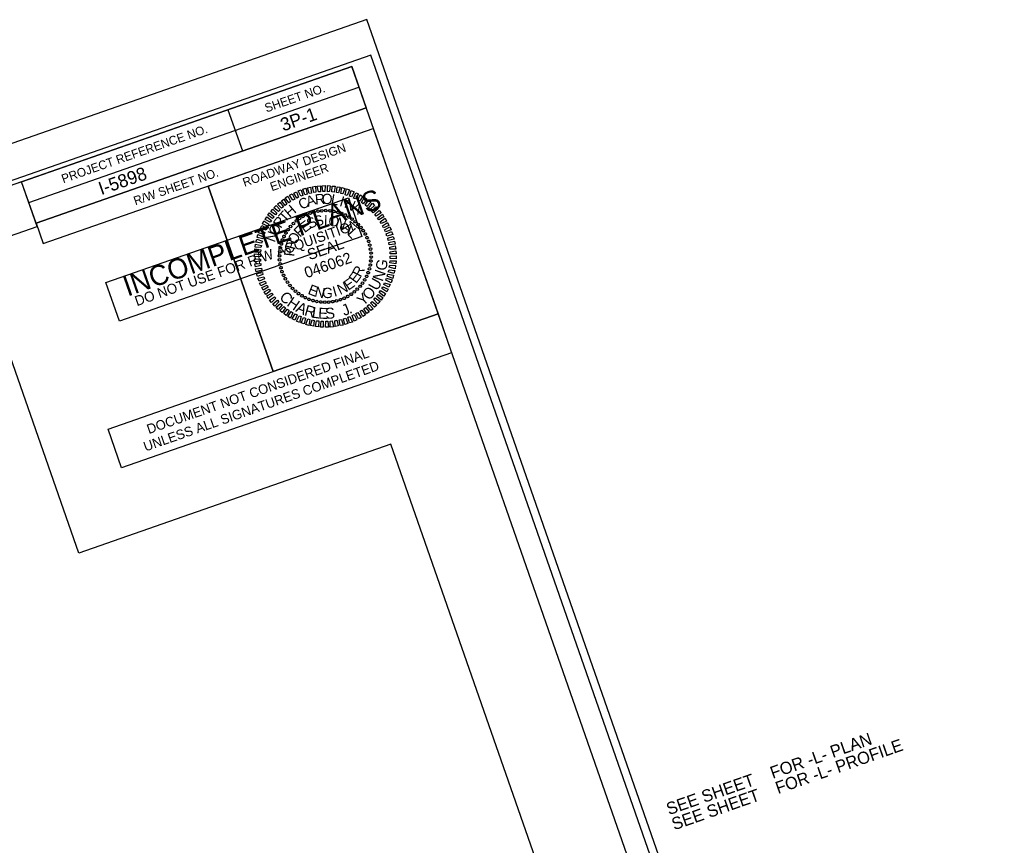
# Model space of a CAD drawing. Extents: x 1719383 to 1723601, y 969280 to 972080.
# Drawn here: x 1720774 to 1721334, y 970396 to 970869 of the extents above; entities that cross this region are included whole.
import ezdxf

# ---------------------------------------------------------------- set-up
doc = ezdxf.new("R2010")
doc.units = 0
for name, color, linetype in [('Default', 7, 'Continuous'), ('Old_Level_2', 7, 'Continuous'), ('Prop Dimension', 7, 'Continuous'), ('Prop Dimension Text', 7, 'Continuous'), ('Sheet Clip Boundary CELL', 7, 'Continuous'), ('Sheet Data Field CELL', 7, 'Continuous'), ('Sheet Plan CELL', 7, 'Continuous'), ('Sheet Plot Border Inside CELL', 7, 'Continuous'), ('Sheet Plot Border Outside CELL', 7, 'Continuous'), ('Sheet Sticker Exception Certification CELL', 7, 'Continuous'), ('Sheet Sticker Incomplete CELL', 7, 'Continuous')]:
    doc.layers.add(name, color=color, linetype=linetype)

msp = doc.modelspace()

# ---------------------------------------------------------------- linework, layer by layer
at = {"layer": 'Old_Level_2'}
for p, q in [((1720949.47, 970759.33), (1720949.47, 970759.33)), ((1720934.33, 970754.75), (1720934.33, 970754.75)), ((1720936.34, 970755.94), (1720936.34, 970755.94)), ((1720938.35, 970757.01), (1720938.35, 970757.01)), ((1720940.49, 970757.86), (1720940.49, 970757.86)), ((1720942.7, 970758.51), (1720942.7, 970758.51)), ((1720944.93, 970758.94), (1720944.93, 970758.94)), ((1720947.16, 970759.26), (1720947.16, 970759.26)), ((1720951.76, 970759.17), (1720951.76, 970759.17)), ((1720954.04, 970758.9), (1720954.04, 970758.9)), ((1720956.25, 970758.32), (1720956.25, 970758.32)), ((1720958.46, 970757.63), (1720958.46, 970757.63)), ((1720960.52, 970756.72), (1720960.52, 970756.72)), ((1720962.59, 970755.64), (1720962.59, 970755.64)), ((1720964.45, 970754.38), (1720964.45, 970754.38)), ((1720927.82, 970748.39), (1720927.82, 970748.39)), ((1720929.26, 970750.2), (1720929.26, 970750.2)), ((1720930.82, 970751.89), (1720930.82, 970751.89)), ((1720932.49, 970753.4), (1720932.49, 970753.4)), ((1720966.27, 970752.93), (1720966.27, 970752.93)), ((1720967.95, 970751.38), (1720967.95, 970751.38)), ((1720969.46, 970749.71), (1720969.46, 970749.71)), ((1720925.48, 970744.46), (1720925.48, 970744.46)), ((1720926.55, 970746.53), (1720926.55, 970746.53)), ((1720970.81, 970747.87), (1720970.81, 970747.87)), ((1720972, 970745.85), (1720972, 970745.85)), ((1720973.07, 970743.85), (1720973.07, 970743.85)), ((1720923.3, 970737.97), (1720923.3, 970737.97)), ((1720923.87, 970740.19), (1720923.87, 970740.19)), ((1720924.56, 970742.4), (1720924.56, 970742.4)), ((1720973.92, 970741.71), (1720973.92, 970741.71)), ((1720974.57, 970739.5), (1720974.57, 970739.5)), ((1720975, 970737.26), (1720975, 970737.26)), ((1720922.86, 970733.41), (1720922.86, 970733.41)), ((1720923.02, 970735.7), (1720923.02, 970735.7)), ((1720949.13, 970733.07), (1720949.13, 970733.07)), ((1720975.32, 970735.04), (1720975.32, 970735.04)), ((1720975.39, 970732.72), (1720975.39, 970732.72)), ((1720922.94, 970731.1), (1720922.94, 970731.1)), ((1720923.26, 970728.87), (1720923.26, 970728.87)), ((1720923.69, 970726.64), (1720923.69, 970726.64)), ((1720974.39, 970725.94), (1720974.39, 970725.94)), ((1720974.96, 970728.16), (1720974.96, 970728.16)), ((1720975.24, 970730.44), (1720975.24, 970730.44)), ((1720924.34, 970724.42), (1720924.34, 970724.42)), ((1720925.19, 970722.28), (1720925.19, 970722.28)), ((1720926.26, 970720.28), (1720926.26, 970720.28)), ((1720972.78, 970721.67), (1720972.78, 970721.67)), ((1720973.69, 970723.74), (1720973.69, 970723.74)), ((1720927.45, 970718.27), (1720927.45, 970718.27)), ((1720928.8, 970716.43), (1720928.8, 970716.43)), ((1720930.3, 970714.75), (1720930.3, 970714.75)), ((1720969, 970715.93), (1720969, 970715.93)), ((1720970.44, 970717.74), (1720970.44, 970717.74)), ((1720971.71, 970719.6), (1720971.71, 970719.6)), ((1720931.99, 970713.2), (1720931.99, 970713.2)), ((1720933.81, 970711.75), (1720933.81, 970711.75)), ((1720935.67, 970710.49), (1720935.67, 970710.49)), ((1720937.74, 970709.41), (1720937.74, 970709.41)), ((1720959.91, 970709.12), (1720959.91, 970709.12)), ((1720961.91, 970710.2), (1720961.91, 970710.2)), ((1720963.93, 970711.38), (1720963.93, 970711.38)), ((1720965.77, 970712.73), (1720965.77, 970712.73)), ((1720967.44, 970714.24), (1720967.44, 970714.24)), ((1720939.8, 970708.5), (1720939.8, 970708.5)), ((1720942.01, 970707.81), (1720942.01, 970707.81)), ((1720944.22, 970707.24), (1720944.22, 970707.24)), ((1720946.5, 970706.96), (1720946.5, 970706.96)), ((1720948.79, 970706.8), (1720948.79, 970706.8)), ((1720951.1, 970706.88), (1720951.1, 970706.88)), ((1720953.32, 970707.19), (1720953.32, 970707.19)), ((1720955.56, 970707.63), (1720955.56, 970707.63)), ((1720957.77, 970708.28), (1720957.77, 970708.28))]:
    msp.add_line(p, q, dxfattribs=at)
for points in [[(1720935.08, 970767.51), (1720933.66, 970770.61), (1720935.3, 970771.16), (1720936.28, 970767.9)], [(1720937.46, 970768.33), (1720936.28, 970771.52), (1720937.92, 970772.07), (1720938.65, 970768.72)], [(1720939.96, 970769.09), (1720938.98, 970772.35), (1720940.71, 970772.65), (1720941.21, 970769.33)], [(1720942.46, 970769.57), (1720941.75, 970772.87), (1720943.46, 970773.22), (1720943.7, 970769.85)], [(1720945.17, 970769.95), (1720944.48, 970773.32), (1720946.29, 970773.54), (1720946.29, 970770.08)], [(1720947.76, 970770.18), (1720947.37, 970773.49), (1720949.07, 970773.56), (1720948.91, 970770.22)], [(1720950.29, 970770.11), (1720950.28, 970773.62), (1720951.87, 970773.54), (1720951.54, 970770.18)], [(1720952.84, 970769.99), (1720953, 970773.34), (1720954.77, 970773.21), (1720954.12, 970769.85)], [(1720955.51, 970769.7), (1720955.81, 970772.98), (1720957.59, 970772.69), (1720956.66, 970769.45)], [(1720957.91, 970769.08), (1720958.58, 970772.56), (1720960.24, 970772), (1720959.21, 970768.89)], [(1720960.47, 970768.35), (1720961.29, 970771.72), (1720962.96, 970771.11), (1720961.65, 970768.01)], [(1720962.89, 970767.52), (1720963.96, 970770.81), (1720965.58, 970770.07), (1720964.1, 970767.12)], [(1720926.2, 970762.28), (1720923.99, 970764.81), (1720925.34, 970765.81), (1720927.1, 970763.01)], [(1720928.32, 970763.79), (1720926.15, 970766.5), (1720927.69, 970767.46), (1720929.26, 970764.42)], [(1720930.48, 970765.2), (1720928.53, 970768.05), (1720930.1, 970768.79), (1720931.6, 970765.78)], [(1720932.72, 970766.36), (1720931.02, 970769.3), (1720932.62, 970770.11), (1720933.85, 970766.94)], [(1720965.29, 970766.45), (1720966.55, 970769.53), (1720968.16, 970768.79), (1720966.32, 970765.94)], [(1720967.66, 970765.32), (1720969.1, 970768.36), (1720970.62, 970767.41), (1720968.71, 970764.59)], [(1720969.84, 970763.95), (1720971.48, 970766.89), (1720972.94, 970765.82), (1720970.77, 970763.23)], [(1720971.86, 970762.41), (1720973.77, 970765.23), (1720975.24, 970764.1), (1720972.91, 970761.68)], [(1720920.63, 970756.83), (1720917.84, 970758.81), (1720919.07, 970760.16), (1720921.35, 970757.76)], [(1720922.31, 970758.79), (1720919.73, 970760.95), (1720920.99, 970762.2), (1720923.22, 970759.63)], [(1720924.09, 970760.61), (1720921.76, 970762.99), (1720923.02, 970764.12), (1720925.2, 970761.36)], [(1720973.93, 970760.72), (1720976.04, 970763.45), (1720977.24, 970762.16), (1720974.86, 970760)], [(1720975.69, 970758.97), (1720978.04, 970761.51), (1720979.26, 970760.18), (1720976.58, 970758.07)], [(1720977.42, 970756.99), (1720979.94, 970759.37), (1720981.04, 970758.05), (1720978.29, 970756.14)], [(1720917.61, 970752.65), (1720914.63, 970754.22), (1720915.57, 970755.74), (1720918.3, 970753.63)], [(1720918.93, 970754.81), (1720916.19, 970756.64), (1720917.12, 970758.04), (1720919.79, 970755.79)], [(1720979.08, 970754.93), (1720981.8, 970757.21), (1720982.69, 970755.7), (1720979.8, 970754.02)], [(1720980.53, 970752.79), (1720983.28, 970754.86), (1720984.19, 970753.3), (1720981.21, 970751.87)], [(1720914.19, 970745.59), (1720910.93, 970746.56), (1720911.54, 970748.24), (1720914.55, 970746.73)], [(1720915.22, 970748.09), (1720911.98, 970749.18), (1720912.79, 970750.76), (1720915.71, 970749.16)], [(1720916.21, 970750.4), (1720913.25, 970751.77), (1720913.99, 970753.38), (1720916.88, 970751.43)], [(1720981.84, 970750.6), (1720984.78, 970752.46), (1720985.54, 970750.85), (1720982.47, 970749.49)], [(1720983.01, 970748.35), (1720986.05, 970749.92), (1720986.76, 970748.29), (1720983.54, 970747.21)], [(1720912.66, 970740.68), (1720909.37, 970741.14), (1720909.84, 970742.87), (1720913.12, 970741.85)], [(1720913.41, 970743.18), (1720910.14, 970743.88), (1720910.55, 970745.64), (1720913.7, 970744.35)], [(1720983.96, 970745.92), (1720987.09, 970747.24), (1720987.71, 970745.57), (1720984.39, 970744.74)], [(1720984.82, 970743.45), (1720988.04, 970744.52), (1720988.54, 970742.87), (1720985.15, 970742.23)], [(1720912.11, 970735.52), (1720908.65, 970735.52), (1720908.83, 970737.32), (1720912.2, 970736.78)], [(1720912.26, 970738.14), (1720909.01, 970738.33), (1720909.19, 970740.12), (1720912.5, 970739.28)], [(1720985.44, 970741), (1720988.69, 970741.86), (1720989.11, 970740.12), (1720985.63, 970739.73)], [(1720985.97, 970738.35), (1720989.16, 970739.08), (1720989.43, 970737.29), (1720985.96, 970737.18)], [(1720912.06, 970730.37), (1720908.78, 970729.89), (1720908.53, 970731.63), (1720912.07, 970731.55)], [(1720911.93, 970733), (1720908.56, 970732.76), (1720908.64, 970734.51), (1720912.09, 970734.23)], [(1720986.33, 970733.14), (1720989.7, 970733.38), (1720989.62, 970731.62), (1720986.17, 970731.91)], [(1720986.2, 970735.76), (1720989.48, 970736.25), (1720989.73, 970734.5), (1720986.19, 970734.59)], [(1720912.29, 970727.78), (1720909.1, 970727.05), (1720908.83, 970728.85), (1720912.3, 970728.96)], [(1720912.82, 970725.13), (1720909.57, 970724.27), (1720909.15, 970726.01), (1720912.63, 970726.4)], [(1720986, 970728), (1720989.25, 970727.8), (1720989.07, 970726.01), (1720985.75, 970726.85)], [(1720986.15, 970730.62), (1720989.61, 970730.61), (1720989.43, 970728.82), (1720986.06, 970729.36)], [(1720913.44, 970722.69), (1720910.22, 970721.61), (1720909.72, 970723.27), (1720913.11, 970723.9)], [(1720914.3, 970720.22), (1720911.17, 970718.89), (1720910.55, 970720.56), (1720913.87, 970721.39)], [(1720984.07, 970720.54), (1720987.33, 970719.57), (1720986.72, 970717.9), (1720983.71, 970719.41)], [(1720984.85, 970722.95), (1720988.12, 970722.26), (1720987.71, 970720.49), (1720984.56, 970721.78)], [(1720985.6, 970725.45), (1720988.89, 970725), (1720988.42, 970723.26), (1720985.14, 970724.28)], [(1720915.25, 970717.78), (1720912.21, 970716.21), (1720911.5, 970717.85), (1720914.72, 970718.92)], [(1720916.42, 970715.54), (1720913.48, 970713.67), (1720912.72, 970715.29), (1720915.79, 970716.64)], [(1720982.05, 970715.73), (1720985.01, 970714.37), (1720984.27, 970712.76), (1720981.38, 970714.7)], [(1720983.04, 970718.04), (1720986.28, 970716.96), (1720985.47, 970715.38), (1720982.54, 970716.97)], [(1720917.73, 970713.34), (1720914.98, 970711.27), (1720914.07, 970712.83), (1720917.05, 970714.27)], [(1720919.18, 970711.21), (1720916.46, 970708.92), (1720915.57, 970710.43), (1720918.46, 970712.11)], [(1720920.84, 970709.14), (1720918.32, 970706.76), (1720917.22, 970708.08), (1720919.97, 970709.99)], [(1720977.63, 970709.3), (1720980.42, 970707.32), (1720979.19, 970705.98), (1720976.91, 970708.37)], [(1720979.33, 970711.33), (1720982.07, 970709.49), (1720981.14, 970708.09), (1720978.47, 970710.34)], [(1720980.65, 970713.49), (1720983.63, 970711.91), (1720982.69, 970710.39), (1720979.96, 970712.5)], [(1720922.57, 970707.16), (1720920.22, 970704.62), (1720919, 970705.96), (1720921.68, 970708.06)], [(1720924.33, 970705.41), (1720922.22, 970702.68), (1720921.02, 970703.97), (1720923.4, 970706.13)], [(1720926.4, 970703.73), (1720924.49, 970700.9), (1720923.01, 970702.03), (1720925.35, 970704.45)], [(1720972.06, 970703.85), (1720974.27, 970701.32), (1720972.91, 970700.32), (1720971.15, 970703.13)], [(1720974.17, 970705.52), (1720976.5, 970703.15), (1720975.24, 970702.02), (1720973.05, 970704.77)], [(1720975.95, 970707.35), (1720978.53, 970705.18), (1720977.27, 970703.93), (1720975.03, 970706.51)], [(1720928.42, 970702.19), (1720926.78, 970699.24), (1720925.32, 970700.32), (1720927.49, 970702.9)], [(1720930.6, 970700.82), (1720929.16, 970697.78), (1720927.64, 970698.72), (1720929.55, 970701.54)], [(1720932.97, 970699.68), (1720931.71, 970696.6), (1720930.1, 970697.34), (1720931.94, 970700.2)], [(1720935.37, 970698.62), (1720934.29, 970695.32), (1720932.68, 970696.07), (1720934.16, 970699.01)], [(1720937.79, 970697.78), (1720936.97, 970694.42), (1720935.3, 970695.03), (1720936.6, 970698.13)], [(1720960.8, 970697.8), (1720961.98, 970694.61), (1720960.34, 970694.07), (1720959.61, 970697.42)], [(1720963.17, 970698.62), (1720964.6, 970695.52), (1720962.96, 970694.98), (1720961.98, 970698.24)], [(1720965.54, 970699.77), (1720967.23, 970696.83), (1720965.64, 970696.02), (1720964.41, 970699.19)], [(1720967.78, 970700.94), (1720969.73, 970698.09), (1720968.16, 970697.34), (1720966.66, 970700.35)], [(1720969.94, 970702.34), (1720972.11, 970699.63), (1720970.57, 970698.67), (1720969, 970701.72)], [(1720940.34, 970697.05), (1720939.68, 970693.58), (1720938.02, 970694.14), (1720939.05, 970697.25)], [(1720942.75, 970696.44), (1720942.45, 970693.15), (1720940.67, 970693.44), (1720941.6, 970696.68)], [(1720945.42, 970696.14), (1720945.26, 970692.79), (1720943.49, 970692.92), (1720944.14, 970696.28)], [(1720947.97, 970696.02), (1720947.98, 970692.52), (1720946.39, 970692.6), (1720946.72, 970695.95)], [(1720950.5, 970695.95), (1720950.89, 970692.64), (1720949.19, 970692.57), (1720949.35, 970695.92)], [(1720953.09, 970696.19), (1720953.78, 970692.82), (1720951.97, 970692.59), (1720951.97, 970696.05)], [(1720955.79, 970696.57), (1720956.51, 970693.27), (1720954.8, 970692.91), (1720954.56, 970696.28)], [(1720958.29, 970697.04), (1720959.27, 970693.78), (1720957.55, 970693.48), (1720957.04, 970696.81)]]:
    msp.add_lwpolyline(points, close=True, dxfattribs=at)
for centre, major_axis in [((1720942.67, 970758.49), (-0.185, 0.73)), ((1720944.91, 970758.95), (-0.121, 0.743)), ((1720947.19, 970759.22), (-0.056, 0.751)), ((1720949.47, 970759.29), (0.01, 0.753)), ((1720951.76, 970759.16), (0.075, 0.749)), ((1720954.02, 970758.83), (0.14, 0.74)), ((1720932.54, 970753.38), (-0.476, 0.583)), ((1720934.37, 970754.75), (-0.424, 0.622)), ((1720936.31, 970755.95), (-0.368, 0.657)), ((1720938.36, 970756.98), (-0.309, 0.687)), ((1720940.48, 970757.83), (-0.248, 0.711)), ((1720956.25, 970758.31), (0.204, 0.725)), ((1720958.42, 970757.59), (0.267, 0.704)), ((1720960.52, 970756.69), (0.327, 0.678)), ((1720962.54, 970755.61), (0.385, 0.647)), ((1720964.45, 970754.35), (0.44, 0.611)), ((1720966.25, 970752.94), (0.491, 0.57)), ((1720927.84, 970748.39), (-0.611, 0.44)), ((1720929.26, 970750.19), (-0.57, 0.491)), ((1720930.83, 970751.85), (-0.525, 0.539)), ((1720967.92, 970751.37), (0.539, 0.525)), ((1720969.44, 970749.66), (0.583, 0.476)), ((1720970.81, 970747.83), (0.622, 0.424)), ((1720924.6, 970742.36), (-0.704, 0.267)), ((1720925.51, 970744.46), (-0.678, 0.327)), ((1720926.59, 970746.48), (-0.647, 0.385)), ((1720972.01, 970745.88), (0.657, 0.368)), ((1720973.04, 970743.84), (0.687, 0.309)), ((1720973.89, 970741.71), (0.711, 0.248)), ((1720923.36, 970737.96), (-0.74, 0.14)), ((1720923.89, 970740.19), (-0.725, 0.204)), ((1720974.55, 970739.52), (0.73, 0.185)), ((1720975.02, 970737.28), (0.743, 0.121)), ((1720922.9, 970733.41), (-0.753, 0.01)), ((1720922.97, 970731.12), (-0.751, -0.056)), ((1720923.03, 970735.69), (-0.749, 0.075)), ((1720975.29, 970735.01), (0.751, 0.056)), ((1720975.36, 970732.72), (0.753, -0.01)), ((1720923.24, 970728.85), (-0.743, -0.121)), ((1720923.71, 970726.61), (-0.73, -0.185)), ((1720974.37, 970725.95), (0.725, -0.204)), ((1720974.9, 970728.17), (0.74, -0.14)), ((1720975.23, 970730.44), (0.749, -0.075)), ((1720924.37, 970724.42), (-0.711, -0.248)), ((1720925.22, 970722.29), (-0.687, -0.309)), ((1720926.25, 970720.25), (-0.657, -0.368)), ((1720971.67, 970719.66), (0.647, -0.385)), ((1720972.75, 970721.67), (0.678, -0.327)), ((1720973.66, 970723.77), (0.704, -0.267)), ((1720927.45, 970718.31), (-0.622, -0.424)), ((1720928.82, 970716.47), (-0.583, -0.476)), ((1720930.34, 970714.77), (-0.539, -0.525)), ((1720967.43, 970714.28), (0.525, -0.539)), ((1720969, 970715.95), (0.57, -0.491)), ((1720970.42, 970717.74), (0.611, -0.44)), ((1720932.01, 970713.2), (-0.491, -0.57)), ((1720933.81, 970711.78), (-0.44, -0.611)), ((1720935.72, 970710.53), (-0.385, -0.647)), ((1720937.73, 970709.44), (-0.327, -0.678)), ((1720939.84, 970708.54), (-0.267, -0.704)), ((1720957.78, 970708.31), (0.248, -0.711)), ((1720959.9, 970709.15), (0.309, -0.687)), ((1720961.94, 970710.18), (0.368, -0.657)), ((1720963.89, 970711.39), (0.424, -0.622)), ((1720965.72, 970712.76), (0.476, -0.583)), ((1720942.01, 970707.82), (-0.204, -0.725)), ((1720944.24, 970707.3), (-0.14, -0.74)), ((1720946.5, 970706.97), (-0.075, -0.749)), ((1720948.79, 970706.84), (-0.01, -0.753)), ((1720951.07, 970706.91), (0.056, -0.751)), ((1720953.35, 970707.18), (0.121, -0.743)), ((1720955.59, 970707.65), (0.185, -0.73))]:
    msp.add_ellipse(centre, major_axis=major_axis, ratio=0.999708, dxfattribs=at)
at = {"layer": 'Prop Dimension Text'}
msp.add_lwpolyline([(1720642.59, 970700.82), (1720784.23, 970750.28), (1720775.31, 970775.84), (1720633.67, 970726.38)], close=True, dxfattribs=at)
at = {"layer": 'Sheet Clip Boundary CELL'}
msp.add_lwpolyline([(1719941.4, 969372.44), (1721263.14, 969834), (1720986.7, 970625.64), (1720808.02, 970563.24), (1720738.29, 970762.9), (1719595.23, 970363.73)], close=True, dxfattribs=at)
at = {"layer": 'Sheet Plan CELL'}
for p, q in [((1720779.43, 970763.99), (1720968.3, 970829.93)), ((1720783.58, 970752.16), (1720972.42, 970818.13)), ((1720783.58, 970752.16), (1720972.42, 970818.13)), ((1720893.35, 970816.99), (1720901.64, 970793.4)), ((1720787.7, 970740.37), (1720976.54, 970806.33)), ((1720882.15, 970773.35), (1720919.24, 970667.18)), ((1720783.58, 970752.16), (1720787.7, 970740.37))]:
    msp.add_line(p, q, dxfattribs=at)
for points in [[(1720964.2, 970841.79), (1719548.03, 970347.25), (1719894.2, 969355.96), (1721310.35, 969850.49)], [(1720775.31, 970775.84), (1720964.2, 970841.79), (1720972.42, 970818.13), (1720783.58, 970752.16)], [(1720882.15, 970773.35), (1720976.54, 970806.33), (1721013.65, 970700.11), (1720919.25, 970667.13)]]:
    msp.add_lwpolyline(points, close=True, dxfattribs=at)
at = {"layer": 'Sheet Plot Border Inside CELL'}
msp.add_lwpolyline([(1719750.12, 969302.98), (1721322.96, 969852.25), (1720975.16, 970848.25), (1719402.3, 970299)], close=True, dxfattribs=at)
at = {"layer": 'Sheet Plot Border Outside CELL'}
msp.add_lwpolyline([(1719744.44, 969279.81), (1721333.82, 969834.84), (1720972.81, 970868.62), (1719383.44, 970313.59)], close=True, dxfattribs=at)
at = {"layer": 'Sheet Sticker Exception Certification CELL'}
for p, q in [((1720824.79, 970634.17), (1721013.65, 970700.12)), ((1721013.65, 970700.11), (1721021.4, 970677.92)), ((1721021.39, 970677.94), (1720832.54, 970611.99)), ((1720832.54, 970611.99), (1720824.79, 970634.17))]:
    msp.add_line(p, q, dxfattribs=at)
at = {"layer": 'Sheet Sticker Incomplete CELL'}
msp.add_lwpolyline([(1720831.31, 970696.02), (1720823.56, 970718.2), (1720962.34, 970766.67), (1720970.09, 970744.48)], close=True, dxfattribs=at)

# ---------------------------------------------------------------- texts
at = {"layer": 'Default'}
for s, rotation, p in [('G', 81.0495, (1720983.99, 970724.59)), ('U', 60.6845, (1720978.86, 970712.99)), ('N', 70.4786, (1720981.84, 970718.34)), ('O', 49.291, (1720974.31, 970707.52)), ('C', 316.4496, (1720922.39, 970709.19)), ('H', 325.8933, (1720926.67, 970705.12)), ('Y', 41.4923, (1720970.61, 970704.34)), ('A', 335.7331, (1720931.77, 970701.69)), ('R', 344.4458, (1720936.72, 970699.42)), ('L', 351.818, (1720941.14, 970698.1)), ('E', 358.0022, (1720944.96, 970697.45)), ('S', 5.0088, (1720949.33, 970697.2)), ('J', 22.2818, (1720959.97, 970698.87)), ('.', 27.4637, (1720963.01, 970699.99))]:
    msp.add_text(s, height=6.27, rotation=rotation, dxfattribs=at).set_placement(p)
at = {"layer": 'Old_Level_2'}
for s, height, rotation, p in [('C', 5.9, 26.4696, (1720935.48, 970759.63)), ('A', 5.9, 19.27, (1720939.25, 970761.36)), ('R', 5.9, 4.8708, (1720943.44, 970762.68)), ('O', 5.9, 357.6709, (1720947, 970763.16)), ('L', 5.9, 350.4706, (1720951.99, 970762.94)), ('I', 5.9, 343.2699, (1720956.83, 970762.05)), ('N', 5.9, 336.0686, (1720959.5, 970761.3)), ('T', 5.9, 48.0695, (1720926.16, 970752.12)), ('H', 5.9, 40.8692, (1720928.75, 970754.92)), ('A', 5.9, 328.8669, (1720963.46, 970759.48)), ('R', 5.9, 55.2702, (1720923.62, 970748.74)), ('E', 5.9, 36.8608, (1720937.28, 970746.31)), ('S', 5.9, 27.5053, (1720940.28, 970748.59)), ('S', 5.9, 18.1501, (1720943.8, 970749.94)), ('I', 5.9, 359.4393, (1720948.27, 970750.81)), ('O', 5.9, 350.0832, (1720950.49, 970750.84)), ('N', 5.9, 340.7263, (1720954.5, 970750.09)), ('O', 5.9, 62.4715, (1720921.36, 970744.45)), ('F', 5.9, 46.2168, (1720934.68, 970743.68)), ('A', 5.9, 322.01, (1720958.23, 970748.58)), ('L', 5.9, 312.6506, (1720961.4, 970745.9)), ('N', 5.9, 69.6732, (1720920.15, 970740.77)), ('R', 5.9, 74.2894, (1720931.68, 970736.55)), ('O', 5.9, 64.931, (1720932.51, 970739.59)), ('SEAL', 6.273, 19.2497, (1720940.08, 970730.84)), ('P', 5.9, 83.6486, (1720931.27, 970732.83)), ('046062', 6.275, 19.2497, (1720938.42, 970720.52)), ('R', 5.9, 62.7311, (1720969.39, 970720.76)), ('E', 5.9, 34.6615, (1720962.26, 970713.33)), ('E', 5.9, 53.3738, (1720966.76, 970717.16)), ('E', 5.9, 338.5266, (1720938.7, 970711.78)), ('N', 5.9, 347.8837, (1720942.62, 970710.21)), ('G', 5.9, 357.24, (1720947.17, 970709.38)), ('I', 5.9, 15.9509, (1720954.28, 970709.89)), ('N', 5.9, 25.3061, (1720957.62, 970710.95))]:
    msp.add_text(s, height=height, rotation=rotation, dxfattribs=at).set_placement(p)
at = {"layer": 'Prop Dimension'}
for s, p in [('SEE SHEET    FOR -L- PLAN ', (1721145.78, 970413.25)), ('SEE SHEET    FOR -L- PROFILE', (1721148.8, 970404.59))]:
    msp.add_text(s, height=7, rotation=19.2497, dxfattribs=at).set_placement(p)
at = {"layer": 'Sheet Data Field CELL'}
for s, p in [('3P-1', (1720925, 970804.54)), ('  I-5898 ', (1720815.6, 970766.27))]:
    msp.add_text(s, height=7.5, rotation=19.2497, dxfattribs=at).set_placement(p)
at = {"layer": 'Sheet Plan CELL'}
for s, height, p in [('SHEET NO.', 5, (1720915.46, 970815.42)), ('PROJECT REFERENCE NO.', 5.0001, (1720799.14, 970774.92)), ('ROADWAY DESIGN', 5.0001, (1720902.85, 970772.85)), ('R/W SHEET NO.', 5.0001, (1720840.42, 970762.28)), ('ENGINEER', 5, (1720918.54, 970770.34))]:
    msp.add_text(s, height=height, rotation=19.2497, dxfattribs=at).set_placement(p)
at = {"layer": 'Sheet Sticker Exception Certification CELL'}
for s, p in [('DOCUMENT NOT CONSIDERED FINAL', (1720848.1, 970631.35)), ('UNLESS ALL SIGNATURES COMPLETED', (1720846.21, 970621.37))]:
    msp.add_text(s, height=5.5, rotation=19.2497, dxfattribs=at).set_placement(p)
at = {"layer": 'Sheet Sticker Incomplete CELL'}
for s, height, p in [('INCOMPLETE PLANS', 11.52, (1720835.9, 970710.01)), ('DO NOT USE FOR R/W ACQUISITION', 5.76, (1720841.26, 970704.52))]:
    msp.add_text(s, height=height, rotation=19.2497, dxfattribs=at).set_placement(p)

doc.saveas('drawing.dxf')
